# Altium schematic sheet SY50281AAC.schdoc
size 127 x 101 mm
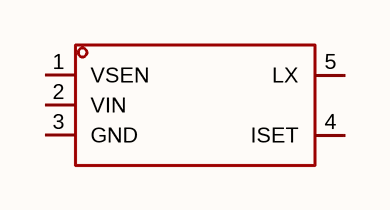
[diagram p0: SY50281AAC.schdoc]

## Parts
U?  sy50281aac  [SOT-23-5_L2.9-W1.6-P0.95-LS2.8-BL]  (value not drawn)

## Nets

Not connected (* = marked no-connect by the designer): U? 1(VSEN) 2(VIN) 3(GND) 4(ISET) 5(LX)

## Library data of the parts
U? = sy50281aac: 功能类型:降压型;工作电压:8V~15.4V;输出电压:12V;输出电流:-;输出类型:可调;; Manufacturer: Silergy(矽力杰); AddInBom: yes; ModelId: 018c57e721114987ae90467fe9f1d259; ModelTransform: 114.96,110.236,0,0,0,0,0,0,0; Function: 降压型; Output Voltage: 12V; Frequency - Switching: 45kHz; Number of Outputs: 1; Topology: 降压式; Quiescent Current: 15uA; Switch tube (built-in/external): 内置; Output Type: 可调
